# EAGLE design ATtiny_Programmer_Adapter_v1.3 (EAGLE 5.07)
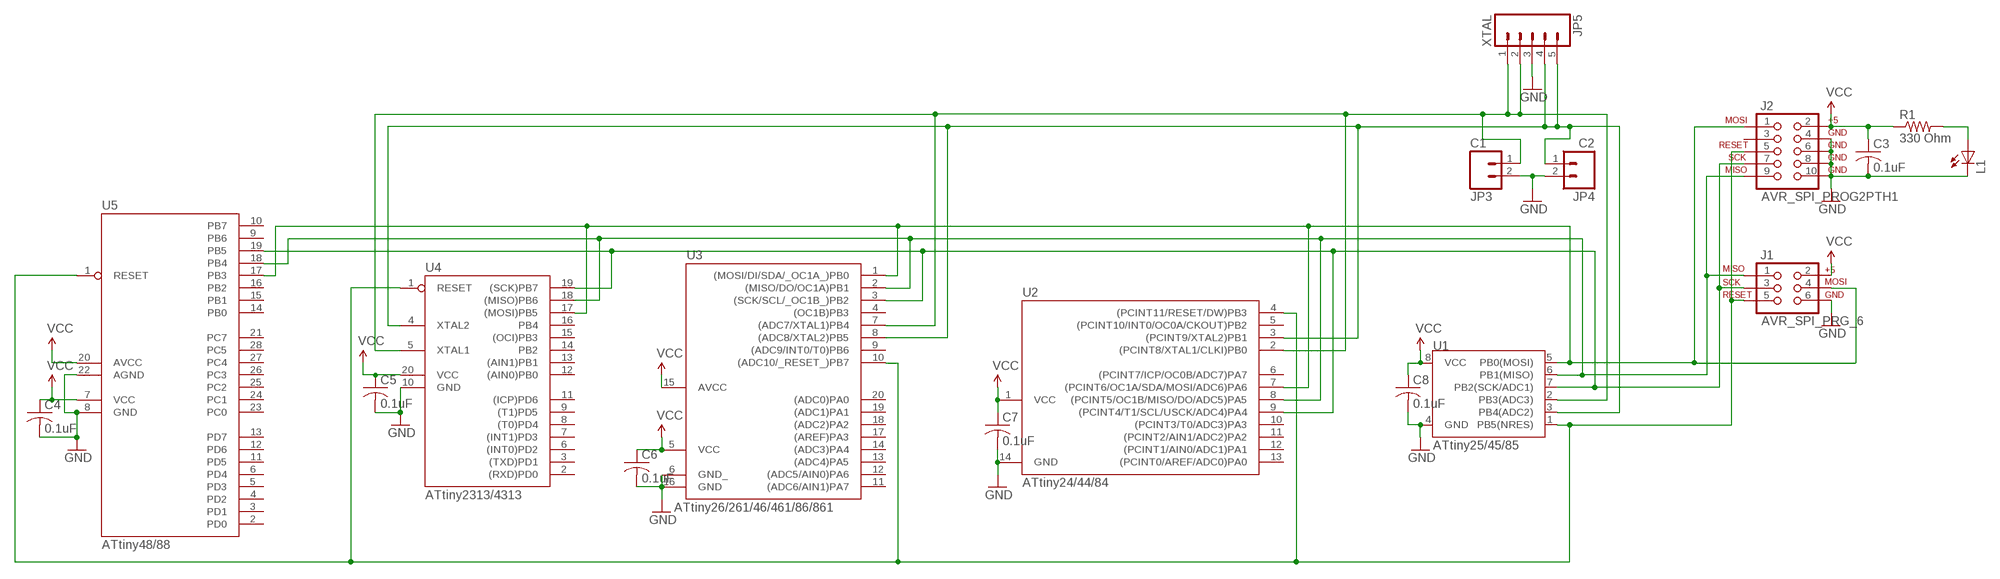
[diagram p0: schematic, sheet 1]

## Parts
C3  0.1uF  C-USC0805K  [C0805K]
C4  0.1uF  C-USC0805K  [C0805K]
C5  0.1uF  C-USC0805K  [C0805K]
C6  0.1uF  C-USC0805K  [C0805K]
C7  0.1uF  C-USC0805K  [C0805K]
C8  0.1uF  C-USC0805K  [C0805K]
J1  AVR_SPI_PRG_6  [2X3_2]
J2  AVR_SPI_PROG2PTH1  [AVR_ICSP_3]
JP3  C1  M02PTH  [1X02]
JP4  C2  M02PTH  [1X02]
JP5  XTAL  M05PTH  [1X05]
L1  LEDCHIP-LED0805  [CHIP-LED0805]
R1  330 Ohm  R-US_R0805_2  [R0805_2]
U1  ATtiny25/45/85  ATTINY45DIP8  [DIP08]
U2  ATtiny24/44/84  TINY24/44/84  [DIP14]
U3  ATtiny26/261/46/461/86/861  TINY26  [DIP20]
U4  ATtiny2313/4313  AT90S2313  [DIP20]
U5  ATtiny48/88  TINY48-88DIP28  [DIP28]

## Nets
GND: C3.2 C4.2 C5.2 C6.2 C7.2 C8.2 J1.6 J2.4 J2.6 J2.8 J2.10 JP3.2 JP4.2 JP5.3 L1.C U1.4(GND) U2.14(GND) U3.6(GND_) U3.16(GND) U4.10(GND) U5.8(GND) U5.22(AGND)
MISO: J1.1 J2.9 U1.6(PB1(MISO)) U2.8((PCINT5/OC1B/MISO/DO/ADC5)PA5) U3.2((MISO/DO/OC1A)PB1) U4.18((MISO)PB6) U5.18(PB4)
MOSI: J1.4 J2.1 U1.5(PB0(MOSI)) U2.7((PCINT6/OC1A/SDA/MOSI/ADC6)PA6) U3.1((MOSI/DI/SDA/_OC1A_)PB0) U4.17((MOSI)PB5) U5.17(PB3)
N$1: JP3.1 JP5.1 JP5.2 U1.2(PB3(ADC3)) U2.2((PCINT8/XTAL1/CLKI)PB0) U3.7((ADC7/XTAL1)PB4) U4.5(XTAL1)
N$6: L1.A R1.2
N$10: JP4.1 JP5.4 JP5.5 U1.3(PB4(ADC2)) U2.3((PCINT9/XTAL2)PB1) U3.8((ADC8/XTAL2)PB5) U4.4(XTAL2)
RESET: J1.5 J2.5 U1.1(PB5(NRES)) U2.4((PCINT11/RESET/DW)PB3) U3.10((ADC10/_RESET_)PB7) U4.1(RESET) U5.1(RESET)
SCK: J1.3 J2.7 U1.7(PB2(SCK/ADC1)) U2.9((PCINT4/T1/SCL/USCK/ADC4)PA4) U3.3((SCK/SCL/_OC1B_)PB2) U4.19((SCK)PB7) U5.19(PB5)
VCC: C3.1 C4.1 C5.1 C6.1 C7.1 C8.1 J1.2 J2.2 R1.1 U1.8(VCC) U2.1(VCC) U3.5(VCC) U3.15(AVCC) U4.20(VCC) U5.7(VCC) U5.20(AVCC)
Unconnected: J2.3 U2.5((PCINT10/INT0/OC0A/CKOUT)PB2) U2.6((PCINT7/ICP/OC0B/ADC7)PA7) U2.10((PCINT3/T0/ADC3)PA3) U2.11((PCINT2/AIN1/ADC2)PA2) U2.12((PCINT1/AIN0/ADC1)PA1) U2.13((PCINT0/AREF/ADC0)PA0) U3.4((OC1B)PB3) U3.9((ADC9/INT0/T0)PB6) U3.11((ADC6/AIN1)PA7) U3.12((ADC5/AIN0)PA6) U3.13((ADC4)PA5) U3.14((ADC3)PA4) U3.17((AREF)PA3) U3.18((ADC2)PA2) U3.19((ADC1)PA1) U3.20((ADC0)PA0) U4.2((RXD)PD0) U4.3((TXD)PD1) U4.6((INT0)PD2) U4.7((INT1)PD3) U4.8((T0)PD4) U4.9((T1)PD5) U4.11((ICP)PD6) U4.12((AIN0)PB0) U4.13((AIN1)PB1) U4.14(PB2) U4.15((OCI)PB3) U4.16(PB4) U5.2(PD0) U5.3(PD1) U5.4(PD2) U5.5(PD3) U5.6(PD4) U5.9(PB6) U5.10(PB7) U5.11(PD5) U5.12(PD6) U5.13(PD7) U5.14(PB0) U5.15(PB1) U5.16(PB2) U5.21(PC7) U5.23(PC0) U5.24(PC1) U5.25(PC2) U5.26(PC3) U5.27(PC4) U5.28(PC5)

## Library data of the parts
C3-C8 = adafruit:C-US: CAPACITOR, American symbol
J1 = SparkFun:AVR_SPI_PRG_6: AVR ISP 6 Pin This is the reduced ISP connector for AVR programming. Common on Arduino. This footprint will take up less PCB space and can be used with a 10-pin to 6-pin adapter such as SKU: BOB-08508
J2 = SparkFun:AVR_SPI_PROG2: AVR ICSP Header This is the standard AVR In Circuit Serial Programming header. Minimal, but includes pin one indicator. Works with standard Olimex programmers. Also look for the 6-pin reduced version. Spark Fun Electronics SKU: PRT-00778
JP3 JP4 = SparkFun:M02: Header 2
JP5 = SparkFun:M05: Header 5 Standard 5-pin 0.1" header. Use with straight break away headers (SKU : PRT-00116), right angle break away headers (PRT-00553), swiss pins (PRT-00743), machine pins (PRT-00117), and female headers (PRT-00115). Molex polarized connector foot print use with SKU : PRT-08230 with associated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
L1 = adafruit:LED: LED
R1 = adafruit:R-US_: RESISTOR, American symbol
U1 = SparkFun:ATTINY45: Atmel ATTiny45
U2 = avr-5:TINY24/44/84
U3 = avr-5:TINY26
U4 = avr-5:AT90S2313: MICROCONTROLLER 2 Kbytes FLASH 128 bytes SRAM 128 bytes EEPROM UART
U5 = atmel:TINY48-88

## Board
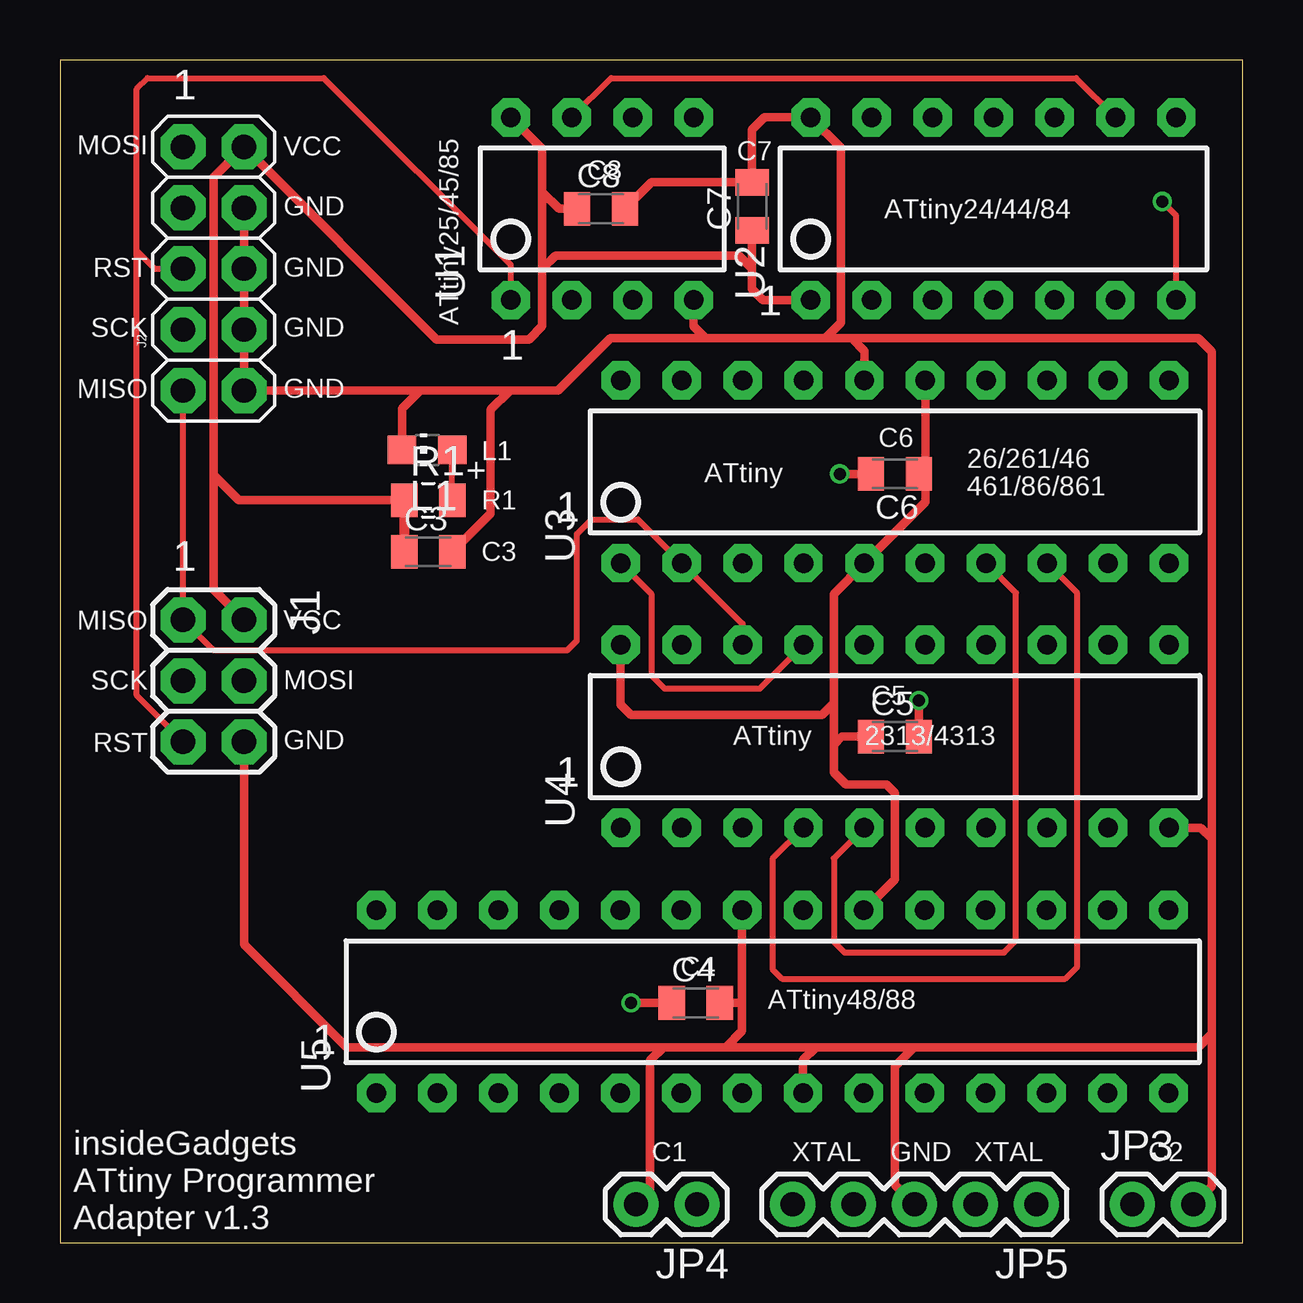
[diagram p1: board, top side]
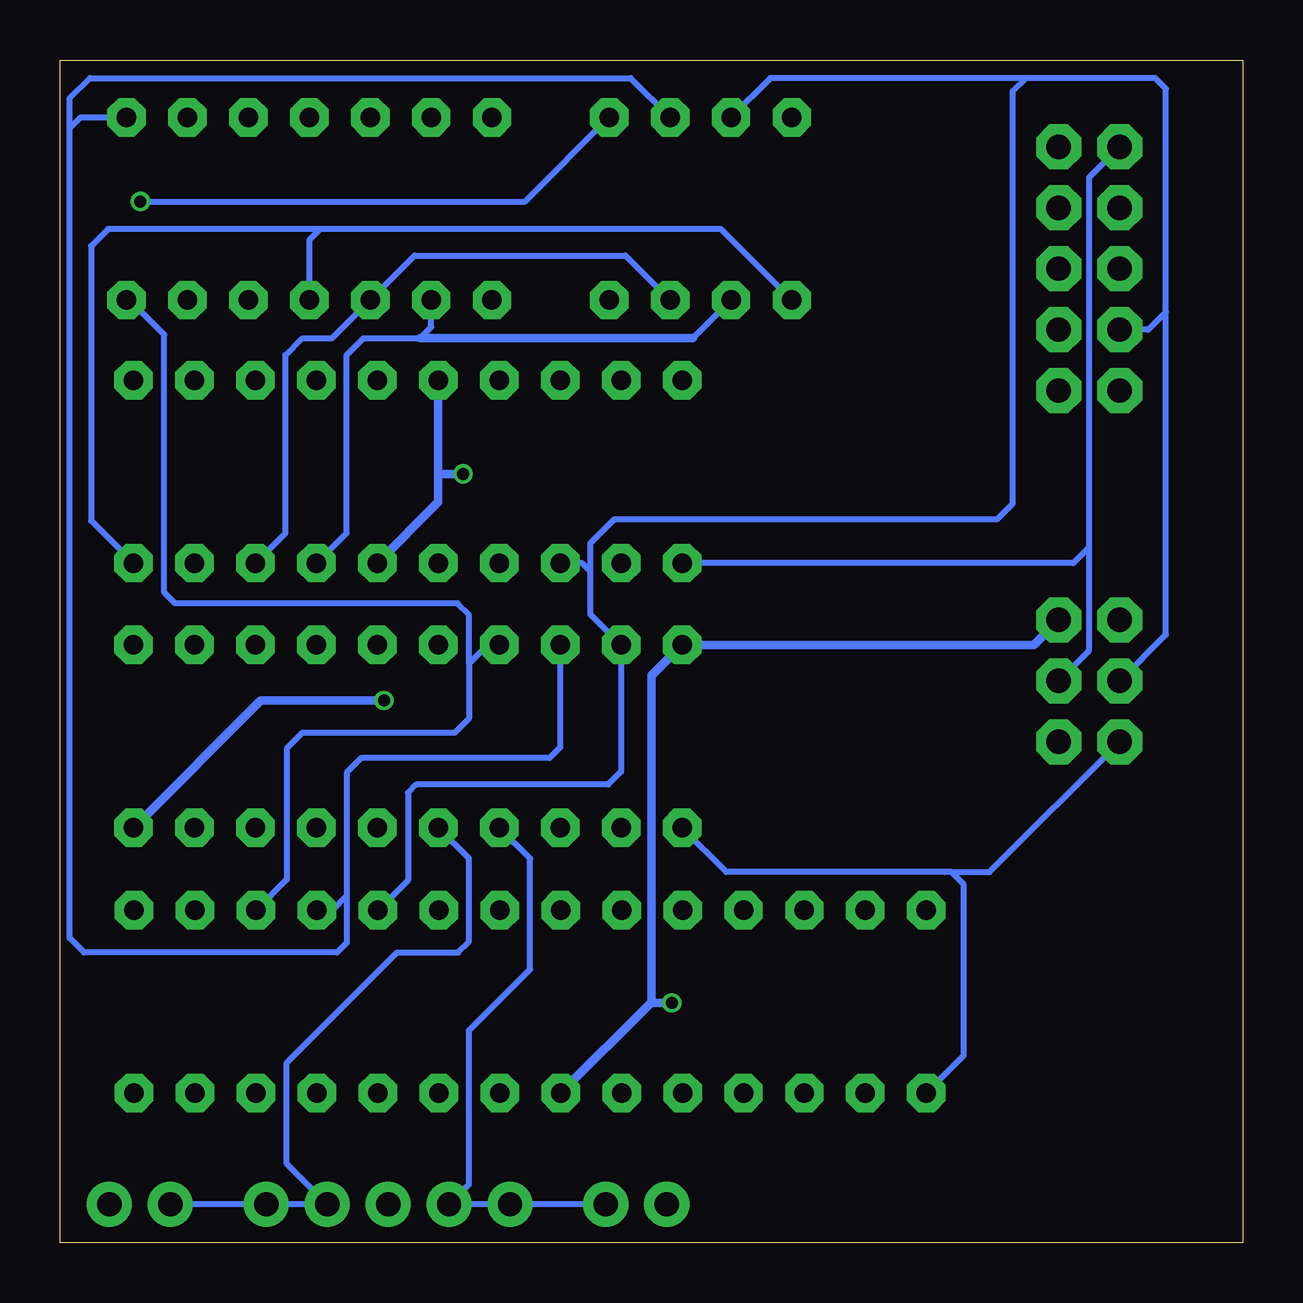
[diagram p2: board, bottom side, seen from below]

Size 49.3 x 49.3 mm. Coordinates in mm from the lower left corner, seen from the top.
Outline: 0,0 49.3,0 49.3,49.3 0,49.3 0,0
Copper layers (1*16): Top 0.035mm / dielectric 1.5mm / Bottom 0.035mm
Design rules "ITead_rule": minimum track width 6mil, minimum drill 12mil, track to track 6mil, track to pad 6mil, pad to pad 6mil, via to via 6mil, smd to smd 0mil, copper to edge 10mil, drill to drill 10mil, minimum pad ring 10mil, minimum via ring 6mil, stop-mask expansion 2mil, vias tented up to drill 100mil, thermal gap 10mil

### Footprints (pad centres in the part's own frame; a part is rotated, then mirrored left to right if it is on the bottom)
C0805K = smd 1.1 x 1.4: 1 -1,0; 2 1,0
2X3_2 = drill 1.016 pad 1.88 octagon: 1 -2.54,-1.27; 2 -2.54,1.27; 3 0,-1.27; 4 0,1.27; 5 2.54,-1.27; 6 2.54,1.27
AVR_ICSP_3 = drill 1.016 pad 1.88 octagon: 1 -1.27,5.08; 2 1.27,5.08; 3 -1.27,2.54; 4 1.27,2.54; 5 -1.27,0; 6 1.27,0; 7 -1.27,-2.54; 8 1.27,-2.54; 9 -1.27,-5.08; 10 1.27,-5.08
1X02 = drill 1.016 pad 1.88 round: 1 0,0; 2 2.54,0
1X05 = drill 1.016 pad 1.88 round: 1 0,0; 2 2.54,0; 3 5.08,0; 4 7.62,0; 5 10.16,0
CHIP-LED0805 = smd 1.2 x 1.2: A 0,-1.05; C 0,1.05
R0805_2 = smd 1.1 x 1.4: 1 -1,0; 2 1,0
DIP08 = drill 0.813 pad 1.6 octagon: 1 -3.81,-3.81; 2 -1.27,-3.81; 3 1.27,-3.81; 4 3.81,-3.81; 5 3.81,3.81; 6 1.27,3.81; 7 -1.27,3.81; 8 -3.81,3.81
DIP14 = drill 0.813 pad 1.6 octagon: 1 -3.81,-3.81; 2 -1.27,-3.81; 3 1.27,-3.81; 4 3.81,-3.81; 5 6.35,-3.81; 6 8.89,-3.81; 7 11.43,-3.81; 8 11.43,3.81; 9 8.89,3.81; 10 6.35,3.81; 11 3.81,3.81; 12 1.27,3.81; 13 -1.27,3.81; 14 -3.81,3.81
DIP20 = drill 0.813 pad 1.6 octagon: 1 -11.43,-3.81; 2 -8.89,-3.81; 3 -6.35,-3.81; 4 -3.81,-3.81; 5 -1.27,-3.81; 6 1.27,-3.81; 7 3.81,-3.81; 8 6.35,-3.81; 9 8.89,-3.81; 10 11.43,-3.81; 11 11.43,3.81; 12 8.89,3.81; 13 6.35,3.81; 14 3.81,3.81; 15 1.27,3.81; 16 -1.27,3.81; 17 -3.81,3.81; 18 -6.35,3.81; 19 -8.89,3.81; 20 -11.43,3.81
DIP28 = drill 0.813 pad 1.6 octagon: 1 -16.51,-3.81; 2 -13.97,-3.81; 3 -11.43,-3.81; 4 -8.89,-3.81; 5 -6.35,-3.81; 6 -3.81,-3.81; 7 -1.27,-3.81; 8 1.27,-3.81; 9 3.81,-3.81; 10 6.35,-3.81; 11 8.89,-3.81; 12 11.43,-3.81; 13 13.97,-3.81; 14 16.51,-3.81; 15 16.51,3.81; 16 13.97,3.81; 17 11.43,3.81; 18 8.89,3.81; 19 6.35,3.81; 20 3.81,3.81; 21 1.27,3.81; 22 -1.27,3.81; 23 -3.81,3.81; 24 -6.35,3.81; 25 -8.89,3.81; 26 -11.43,3.81; 27 -13.97,3.81; 28 -16.51,3.81

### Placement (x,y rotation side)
C3  15.35,28.8 0 top
C4  26.5,10 0 top
C5  34.8,21.1 0 top
C6  34.8,32.05 180 top
C7  28.85,43.2 90 top
C8  22.55,43.1 0 top
J1  6.4,23.42 270 top
J2  6.4,40.6 0 top
JP3  44.7,1.6 0 top
JP4  26.55,1.6 180 top
JP5  40.7,1.6 180 top
L1  15.3,33.05 90 top
R1  15.35,30.95 0 top
U1  22.6,43.1 0 top
U2  35.1,43.1 0 top
U3  34.8,32.14 0 top
U4  34.8,21.11 0 top
U5  29.7,10.05 0 top

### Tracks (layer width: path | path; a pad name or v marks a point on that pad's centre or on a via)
GND  (via drill 0.5)
  Top 0.254: U2.14 | 26.92,37.7 26.88,37.73 26.85,37.7 | 28.43,10.05 28.38,10
  Top 0.35: U5.8 30.97,7.62 31.5,8.15 | J2.4 J2.6 J2.8 J2.10 15,35.52 | 33,37.7 47.45,37.7 48,37.15 48,16.85 | U1.4 26.41,38.21 26.88,37.73 | U3.16 33.53,37.17 33,37.7 | 25.15,8.15 27.75,8.15 | 27.75,8.15 31.5,8.15 | JP4.2 24.6,2.21 24.6,7.6 25.15,8.15 | 48,8.7 48,16.85 | 31.5,8.15 35.6,8.15 | 48,8.7 47.45,8.15 36.35,8.15 35.6,8.15 | JP3.2 48,2.36 48,8.7 | U5.22 28.43,10.05 28.43,8.83 27.75,8.15 | 33,37.7 31.9,37.7 | 31.9,37.7 26.92,37.7 | 26.85,37.7 22.95,37.7 20.77,35.52 18.75,35.52 | 25.15,8.15 11.95,8.15 7.67,12.43 J1.6 | U2.14 29.36,46.91 28.85,46.4 C7.2 24.65,44.2 C8.2 | v32.5,32.05 C6.2 | v35.8,22.6 C5.2 | 28.38,10 C4.2 | U2.14 32.55,45.64 32.55,38.35 31.9,37.7 | C3.2 17.95,30.4 17.95,34.72 18.75,35.52 | 18.75,35.52 15,35.52 | L1.C 14.25,34.77 15,35.52 | U4.10 47.55,17.3 48,16.85 | JP5.3 34.8,2.42 34.8,7.35 35.6,8.15
  Bottom 0.254: 33.53,32 33.48,32.05
  Bottom 0.35: U3.6 33.53,30.87 33.53,32 U3.16 | 33.48,32.05 v32.5,32.05 | v35.8,22.6 40.93,22.6 U4.10
MISO
  Top 0.254: U4.18 28.45,25.79 U3.2 24.09,30.15 22.15,30.15 21.55,29.55 21.55,25.1 21.15,24.7 6.39,24.7 J1.1 J2.9
  Bottom 0.254: U1.6 25.51,48.55 48.05,48.55 48.9,47.7 48.9,46.45 | 48.9,46.45 48.9,12.7 48.3,12.1 37.75,12.1 37.35,12.5 37.35,14.45 | U4.18 28.45,20.65 28.9,20.2 36.75,20.2 37.35,19.6 37.35,14.45 | U5.18 37.94,13.86 37.35,14.45 | U2.8 48.44,46.91 48.9,46.45
MOSI  (via drill 0.5)
  Top 0.254: U4.17 29.17,23.1 25.2,23.1 24.65,23.65 24.65,27.05 U3.1 | 46.5,39.32 U2.7 46.53,42.82 v45.95,43.4
  Bottom 0.254: U2.7 46.39,39.29 44.95,37.85 44.95,27.1 44.5,26.65 32.72,26.65 32.25,26.18 32.25,24.15 | U4.17 31.48,24.92 32.25,24.15 | 32.25,24.15 32.25,21.85 32.85,21.25 39.2,21.25 39.85,20.6 39.85,15.14 U5.17 | U1.5 29.92,43.4 v45.95,43.4 | 6.4,29 6.4,24.69 J1.4 | 6.4,29 6.4,44.41 J2.1 | U3.1 7.07,28.33 6.4,29
N$1
  Top 0.254: U4.5 32.25,16.02 32.25,12.55 32.7,12.1 39.35,12.1 39.85,12.6 39.85,27.09 U3.7
  Bottom 0.254: 22.92,37.7 U1.2 | U2.2 33.83,38.17 34.3,37.7 36.65,37.7 37.35,37 37.35,29.59 U3.7 | U4.5 32.25,16.02 32.25,12.55 32.7,12.1 35.25,12.1 39.85,7.5 39.85,3.29 JP5.2 JP5.1 JP3.1
  Bottom 0.35: 34.3,37.7 22.92,37.7
N$6
  Top 0.254: R1.2 L1.A
N$10
  Top 0.254: U3.8 42.4,27.08 42.4,11.5 41.9,11 30.1,11 29.7,11.4 29.7,16.01 U4.4
  Bottom 0.254: U3.8 39.9,29.58 39.9,37 39.2,37.7 37.96,37.7 U2.3 34.51,41.15 25.73,41.15 U1.3 | U4.4 29.7,16.01 29.7,11.4 32.25,8.85 32.25,2.43 JP5.4 JP5.5 JP4.1
RESET
  Top 0.254: 3.2,41.35 3.2,22.81 J1.5 | 3.2,41.35 3.2,48.1 3.65,48.55 11,48.55 18.79,40.76 U1.1 | J2.5 3.95,40.6 3.2,41.35
  Bottom 0.254: U1.1 21.75,42.25 38.45,42.25 | 38.45,42.25 47.3,42.25 48,41.55 48,30.1 U3.10 | U2.4 38.91,41.79 38.45,42.25 | U4.1 21.52,15.45 12.4,15.45 12.15,15.45 | 12.15,15.45 11.63,14.93 11.63,7.8 U5.1 | J1.5 10.56,15.45 12.15,15.45
SCK
  Top 0.254: U1.7 22.97,48.55 42.35,48.55 U2.9
  Bottom 0.254: U5.19 34.8,15.11 34.8,18.75 34.45,19.1 26.45,19.1 25.91,19.64 U4.19 27.2,26.2 27.2,28 | U3.3 27.53,28.33 27.2,28 | 27.2,28 27.2,29.15 26.2,30.15 10.25,30.15 9.6,30.8 9.6,48 9.05,48.55 | 3.2,38.8 3.2,48.1 3.65,48.55 9.05,48.55 | 9.05,48.55 19.69,48.55 U1.7 | J2.7 3.94,38.06 3.2,38.8 | J1.3 3.2,25.35 3.2,38.8
VCC  (via drill 0.5)
  Top 0.254: C7.1 28.85,41.73 | 36.07,31.78 C6.1
  Top 0.35: 20.1,40.6 20.65,41.15 28.3,41.15 28.85,40.6 | U4.20 23.37,22.43 23.8,22 31.75,22 32.25,22.5 | 32.25,22.5 32.25,27.05 U3.5 36.07,30.87 36.07,31.78 U3.15 | U5.20 34.8,15.15 34.8,18.75 34.45,19.1 32.75,19.1 32.25,19.6 32.25,20.75 | U1.8 20.1,45.6 20.1,43.8 | 20.1,40.6 20.1,43.8 | 20.1,40.6 20.1,38.2 19.55,37.65 15.7,37.65 J2.2 6.4,44.41 6.4,32 | C8.1 20.8,43.1 20.1,43.8 | 32.25,22.5 32.25,20.75 | C5.1 32.6,21.1 32.25,20.75 | v23.8,10 C4.1 | U2.1 29.31,39.29 28.85,39.75 28.85,40.6 | 28.85,40.6 C7.1 | J1.2 6.4,27.23 6.4,32 | R1.1 7.45,30.95 6.4,32
  Top 0.406: R1.1 C3.1
  Bottom 0.254: U4.20 | 24.65,10.02 24.67,10
  Bottom 0.35: 24.65,10.02 24.65,23.64 U4.20 8.71,24.92 J1.2 | v23.8,10 24.67,10 U5.7

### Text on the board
tPlace: 1 | MOSI | VCC | C7 | C8 | GND | ATtiny24/44/84 | RST | GND | SCK | ATtiny25/45/85 | 1 | GND | 1 | MISO | GND | C6 | L1 | 26/261/46 | 1 | ATtiny | 461/86/861 | R1 | C3 | 1 | MISO | VCC | SCK | MOSI | C5 | RST | GND | 1 | ATtiny 2313/4313 | C4 | 1 | ATtiny48/88 | insideGadgets | C1 | XTAL | GND | XTAL | C2 | ATtiny Programmer | Adapter v1.3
